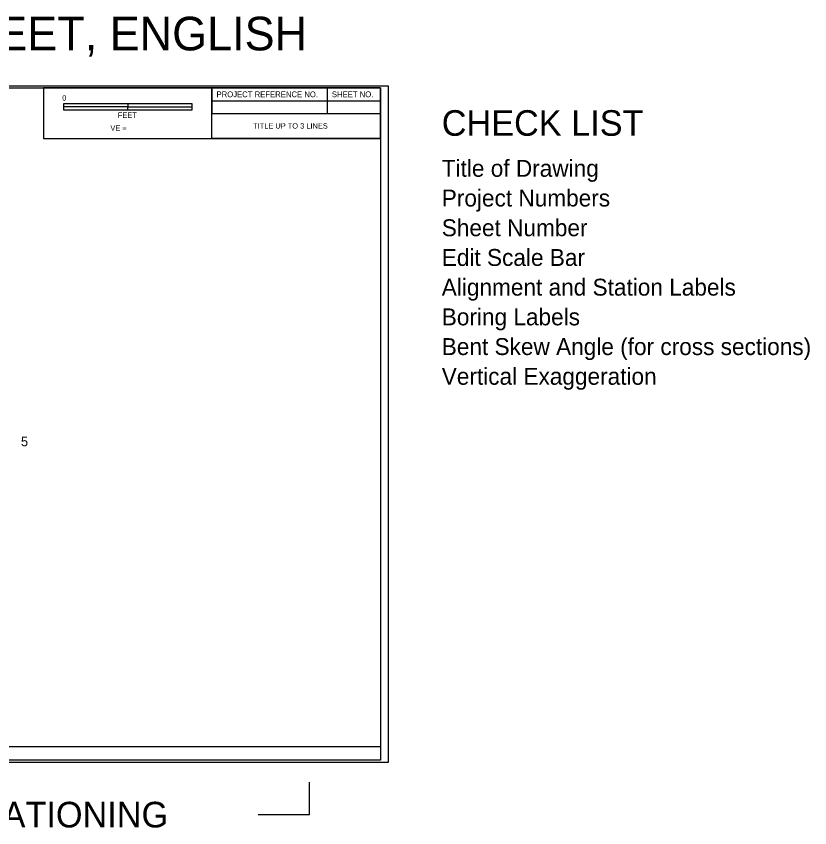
# Model space of a CAD drawing. Extents: x -884 to 1605, y -586 to 681.
# Drawn here: x 366 to 1605, y -586 to 681 of the extents above; entities that cross this region are included whole.
import ezdxf

# ---------------------------------------------------------------- set-up
doc = ezdxf.new("R2010")
doc.units = 0
for name, color, linetype in [('Default', 7, 'Continuous'), ('Geotech Sheets and Borders Cell', 7, 'Continuous'), ('Scratch_Level_0', 7, 'Continuous'), ('Scratch_Level_2', 7, 'Continuous'), ('Scratch_Level_4', 7, 'Continuous'), ('Sheet Plot Border Inside CELL', 7, 'Continuous')]:
    doc.layers.add(name, color=color, linetype=linetype)

msp = doc.modelspace()

# ---------------------------------------------------------------- linework, layer by layer
at = {"layer": 'Geotech Sheets and Borders Cell'}
for p, q in [((851.4, 569.4), (851.4, 529.4)), ((671.3, 549.4), (934.2, 549.4)), ((-565.8, -459), (934.2, -459))]:
    msp.add_line(p, q, dxfattribs=at)
for points in [[(-565.8, 569.4), (934.2, 569.4), (934.2, -480.6), (-565.8, -480.6)], [(408.3, 490.4), (934.2, 490.4), (934.2, 569.4), (408.3, 569.4)], [(671.3, 529.4), (934.2, 529.4), (934.2, 569.4), (671.3, 569.4)], [(671.3, 569.4), (934.2, 569.4), (934.2, 490.4), (671.3, 490.4)], [(439.8, 544.8), (639.8, 544.8), (639.8, 534.8), (439.8, 534.8)], [(439.8, 544.8), (539.8, 544.8), (539.8, 539.8), (439.8, 539.8)], [(539.8, 539.8), (639.8, 539.8), (639.8, 534.8), (539.8, 534.8)]]:
    msp.add_lwpolyline(points, close=True, dxfattribs=at)
at = {"layer": 'Scratch_Level_0'}
msp.add_line((946.7, 572.2), (946.7, 572.2), dxfattribs=at)
at = {"layer": 'Scratch_Level_4'}
msp.add_lwpolyline([(743.3, -565.5), (823.6, -565.5), (823.6, -514.7)], dxfattribs=at)
at = {"layer": 'Sheet Plot Border Inside CELL'}
msp.add_lwpolyline([(-720.9, -483.4), (946.7, -483.4), (946.7, 572.2), (-720.9, 572.2)], close=True, dxfattribs=at)

# ---------------------------------------------------------------- texts
at = {"layer": 'Default'}
msp.add_text('5', height=15, dxfattribs=at).set_placement((373, 9.8))
at = {"layer": 'Geotech Sheets and Borders Cell'}
for s, height, p in [('0', 8.4, (437.4, 549.6)), ('PROJECT REFERENCE NO.', 9, (678.4, 554.9)), ('SHEET NO.', 9, (858.5, 554.9)), ('FEET', 8.4, (524.3, 522.6)), ('VE =  ', 8.4, (512.7, 502.6))]:
    msp.add_text(s, height=height, dxfattribs=at).set_placement(p)
msp.add_text('TITLE UP TO 3 LINES', height=8.4, rotation=360, dxfattribs=at).set_placement((735.5, 505.9))
at = {"layer": 'Scratch_Level_2'}
msp.add_text('STRUCTURE PROFILE SHEET, ENGLISH', height=52.5, dxfattribs=at).set_placement((-533.8, 628))
at = {"layer": 'Scratch_Level_4'}
for s, height, p in [('CHECK LIST', 40, (1030.1, 494.6)), ('Title of Drawing', 26.4, (1030.1, 430.6)), ('Project Numbers', 26.4, (1030.1, 384.2)), ('Sheet Number', 26.4, (1030.1, 337.8)), ('Edit Scale Bar', 26.4, (1030.1, 291.4)), ('Alignment and Station Labels', 26.4, (1030.1, 245)), ('Boring Labels', 26.4, (1030.1, 198.6)), ('Bent Skew Angle (for cross sections)', 26.4, (1030.1, 152.2)), ('Vertical Exaggeration', 26.4, (1030.1, 105.8)), ('EDIT DATA FIELDS FOR STATIONING', 40, (-348.1, -585.5))]:
    msp.add_text(s, height=height, dxfattribs=at).set_placement(p)

doc.saveas('drawing.dxf')
